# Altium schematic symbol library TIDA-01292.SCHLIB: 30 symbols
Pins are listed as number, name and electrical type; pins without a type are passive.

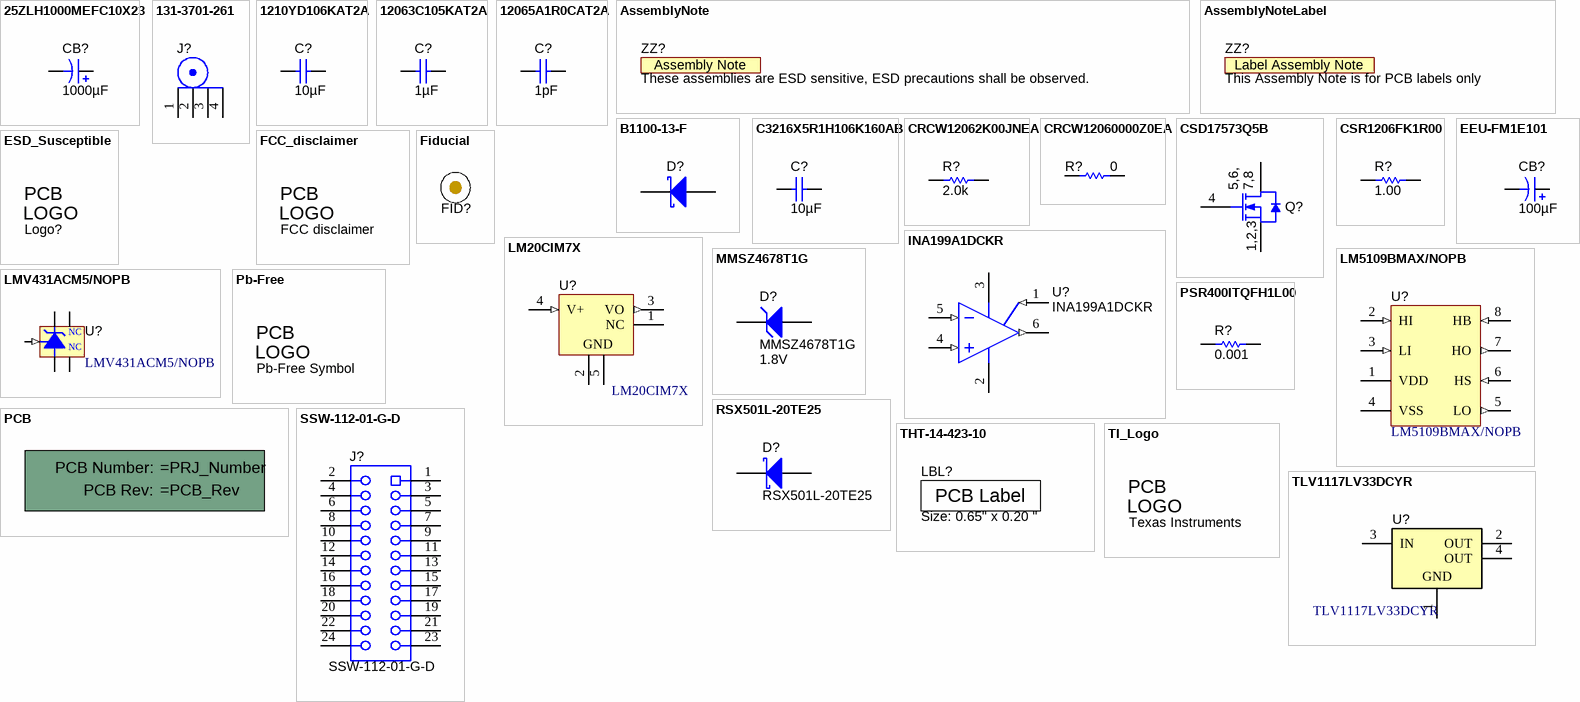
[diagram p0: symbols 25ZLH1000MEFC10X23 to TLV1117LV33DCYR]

## 25ZLH1000MEFC10X23
designator CB?  ValueDisplayed: 1000µF  (hidden comment: 25ZLH1000MEFC10X23)
CAP, AL, 1000 µF, 25 V, +/- 20%, 0.018 ohm, TH; Manufacturer: Rubycon; Polarized: Y; CompType: Capacitor; Value: 1000uF; U/M: EA; Cap_F: 0.001; Tolerance_%: 20; VDC_V: 25; Value2: 25V; ESR_ohm: 0.018; IRMS_A: 2.25; TaMin_C: -40; TaMax_C: 105; Cap_Case: 10x23mm; AEC Category: Q200
signal-integrity model Cap
simulation model Cap
footprint ZLH_1000x2300
pins: 1 +, 2 -

## 131-3701-261
designator J?  (value not drawn)
Connector, SMB,Vertical RCP 0-4GHz, 50 ohm, TH; Manufacturer: Emerson Network Power; SymbolCreator: X0208326
footprint CONN_131-3701-261
pins: 1, 2, 3, 4

## 1210YD106KAT2A
designator C?  ValueDisplayed: 10µF  (hidden comment: 1210YD106KAT2A)
CAP, CERM, 10 µF, 16 V, +/- 10%, X5R, 1210; Manufacturer: AVX; Polarized: N; CompType: Capacitor; Value: 10uF; U/M: EA; Cap_F: 0.00001; Tolerance_%: 10; Value1: Unknown; VDC_V: 16; Value2: 16V; TaMin_C: -55; TaMax_C: 85; Cap_Case: 1210; SizeArea_mm2: 8; SizeAreaWB_mm2: 14.7; SizeX_mm: 3.2; SizeY_mm: 2.5; SizeZ_mm: 2.8; AEC Category: Q200
signal-integrity model Cap
simulation model Cap
footprint 1210_280
pins: 1, 2

## 12063C105KAT2A
designator C?  ValueDisplayed: 1µF  (hidden comment: 12063C105KAT2A)
CAP, CERM, 1 µF, 25 V, +/- 10%, X7R, 1206; Manufacturer: AVX; Polarized: N; CompType: Capacitor; Value: 1uF; U/M: EA; Cap_F: 0.000001; Tolerance_%: 10; ESR_ohm: 0.013; Value1: 0.013 ohm; VDC_V: 25; Value2: 25V; TaMin_C: -55; TaMax_C: 125; Cap_Case: 1206; SizeArea_mm2: 5.12; SizeAreaWB_mm2: 10.92; SizeX_mm: 3.2; SizeY_mm: 1.6; SizeZ_mm: 1.35; AEC Category: Q200
signal-integrity model Cap
simulation model Cap
footprint 1206
footprint 1206M
footprint 1206L
pins: 1, 2

## 12065A1R0CAT2A
designator C?  ValueDisplayed: 1pF  (hidden comment: 12065A1R0CAT2A)
CAP, CERM, 1 pF, 50 V, +/- 25%, C0G/NP0, 1206; Manufacturer: AVX; Polarized: N; CompType: Capacitor; Value: 1pF; U/M: EA; Cap_F: 0.000000000001; Tolerance_%: 25; ESR_ohm: 15.566; Value1: 15.566 ohm; VDC_V: 50; Value2: 50V; TaMin_C: -55; TaMax_C: 125; Cap_Case: 1206; SizeArea_mm2: 5.12; SizeAreaWB_mm2: 10.92; SizeX_mm: 3.2; SizeY_mm: 1.6; SizeZ_mm: 1.35; AEC Category: Q200
signal-integrity model Cap
simulation model Cap
footprint 1206
footprint 1206M
footprint 1206L
pins: 1, 2

## AssemblyNote
designator ZZ?, comment These assemblies are ESD sensitive, ESD precautions shall be observed.  (no BOM)
SymbolCreator: codlsc; CompType: AssemblyNote
footprint AssemblyNote

## AssemblyNoteLabel
designator ZZ?, comment This Assembly Note is for PCB labels only  (no BOM)
SymbolCreator: a0412235
footprint AssemblyNoteLabel

## B1100-13-F
designator D?  (value not drawn)
Diode, Schottky, 100 V, 1 A, SMA; Manufacturer: Diodes Inc.; U/M: EA; Vf_V: 0.79; Value: 100V; Value1: 1A; Value2: 0.79V; Io_A: 1; Vr_V: 100; TJmax_C: 150; RJC_CperW: 25; SizeAreaWB_mm2: 37.3428; SizeArea_mm2: 16.3228; SizeX_mm: 5.59; SizeY_mm: 2.92; SizeZ_mm: 2.87; AEC Category: Q101
signal-integrity model Diode
simulation model DI_B1100
footprint SMA
pins: 1 K, 2 A

## C3216X5R1H106K160AB
designator C?  ValueDisplayed: 10µF  (hidden comment: C3216X5R1H106K160AB)
CAP, CERM, 10 µF, 50 V, +/- 10%, X5R, 1206; Manufacturer: TDK; Polarized: N; CompType: Capacitor; Value: 10uF; U/M: EA; Cap_F: 0.00001; Tolerance_%: 10; Value1: 0.002229 ohm; VDC_V: 50; Value2: 50V; ESR_ohm: 0.002229; IRMS_A: 4.85932; TaMin_C: -55; TaMax_C: 85; Cap_Case: 1206_180; SizeAreaWB_mm2: 10.92; SizeArea_mm2: 5.12; SizeX_mm: 3.2; SizeY_mm: 1.6; SizeZ_mm: 1.8; AEC Category: Q200
signal-integrity model Cap
simulation model Cap
footprint 1206_180
footprint 1206_180M
footprint 1206_180L
pins: 1, 2

## CRCW12062K00JNEA
designator R?  ValueDisplayed: 2.0k  (hidden comment: CRCW12062K00JNEA)
RES, 2.0 k, 5%, 0.25 W, 1206; Manufacturer: Vishay-Dale; CompType: Resistor; Value: 2.0k; Res_ohm: 2000; Value_Code: 2k00; Tolerance_%: 5; Power_W: 0.25; Value2: 0.25W; VDC_V: 200; TempCo: 200 ppm/C; SizeArea_mm2: 5.12; SizeX_mm: 3.2; SizeY_mm: 1.6; SizeZ_mm: 1.35; EIA_Code: E24; U/M: EA; AEC Category: Q200
signal-integrity model Resistor
simulation model Resistor
footprint 1206
footprint 1206M
footprint 1206L
pins: 1, 2

## CRCW12060000Z0EA
designator R?  ValueDisplayed: 0  (hidden comment: CRCW12060000Z0EA)
RES, 0, 5%, 0.25 W, 1206; Manufacturer: Vishay-Dale; CompType: Resistor; Value: 0; Value_Code: 0000; Tolerance_%: 5; Power_W: 0.25; Value2: 0.25W; VDC_V: 200; TempCo: 200 ppm/C; SizeArea_mm2: 5.12; SizeX_mm: 3.2; SizeY_mm: 1.6; SizeZ_mm: 1.35; EIA_Code: E24; U/M: EA; AEC Category: Q200
signal-integrity model Resistor
simulation model Resistor
footprint 1206
footprint 1206M
footprint 1206L
pins: 1, 2

## CSD17573Q5B
designator Q?  (value not drawn)
MOSFET, N-CH, 30 V, 100 A, SON 5x6mm; Manufacturer: Texas Instruments; Alternate Manufacturer: None; U/M: EA; ChType: N; Value: 30V; VdsMax_V: 30; Value1: 0.00145 ohm; Rdson45_ohm: 0.00145; Value2: 49 nC; QgTyp_nC: 49; Vgs_V: 20; IdsMax_A: 100; SizeAreaWB_mm2: 57.51; SizeArea_mm2: 31.11; SizeX_mm: 6.1; SizeY_mm: 5.1; SizeZ_mm: 1.05; AEC Category: Q101
footprint TRANS_NexFET_Q5B
pins: 1 S, 2 S, 3 S, 4 G, 5 D, 6 D, 7 D, 8 D
1 alternate drawing of the same symbol

## CSR1206FK1R00
designator R?  ValueDisplayed: 1.00  (hidden comment: CSR1206FK1R00)
RES, 1.00, 1%, 0.5 W, 1206; Manufacturer: Stackpole Electronics Inc; CompType: Resistor; Value: 1.00; Res_ohm: 1; Value_Code: 1R00; Power_W: 0.5; Value2: 0.5W; TempCo: 100 ppm/C; SizeArea_mm2: 5.12; SizeX_mm: 3.2; SizeY_mm: 1.6; SizeZ_mm: 1.35; EIA_Code: E96; U/M: EA; AEC Category: Q200
signal-integrity model Resistor
simulation model Resistor
footprint 1206
footprint 1206M
footprint 1206L
pins: 1, 2

## EEU-FM1E101
designator CB?  ValueDisplayed: 100µF  (hidden comment: EEU-FM1E101)
CAP, AL, 100 µF, 25 V, +/- 20%, 0.13 ohm, TH; Manufacturer: Panasonic; Polarized: Y; CompType: Capacitor; Value: 100uF; U/M: EA; Cap_F: 0.0001; Tolerance_%: 20; VDC_V: 25; Value2: 25V; ESR_ohm: 0.13; IRMS_A: 0.455; TaMin_C: -40; TaMax_C: 105; Cap_Case: 6.3x11.2; AEC Category: Q200; AEC Qualified: N
signal-integrity model Cap
simulation model Cap
footprint FM_630x1120
pins: 1 +, 2 -

## ESD_Susceptible
designator Logo?, comment ESD Susceptible  (value not drawn)  (no BOM)
ESD Susceptible Symbol; SymbolCreator: a0412235
footprint ESD_Overlay_Large
footprint ESD_Overlay_Medium
footprint ESD_Overlay_Small

## FCC_disclaimer
designator Logo?, comment FCC disclaimer  (no BOM)
FCC_disclaimer; SymbolCreator: codlsc
footprint FCC_disclaimer
footprint FCC_disclaimer_stacked

## Fiducial
designator FID?  (value not drawn)
Fiducial mark.  There is nothing to buy or mount.; SymbolCreator: codlsc
footprint Fiducial10-30
footprint Fiducial10-20
footprint Fiducial15-30
footprint Fiducial20-40
footprint Fiducial6.4-20

## INA199A1DCKR
designator U?
Voltage Output, High or Low Side Measurement, Bi-Directional Zerø-Drift Series Current-Shunt Monitor, DCK0006A (SOT-6); Alternate PartNumber: INA199A1DCKT; Manufacturer: Texas Instruments; SymbolCreator: a0411947; SizeArea_mm2: 4.2; SizeAreaWB_mm2: 9.3; SizeX_mm: 2.1; SizeY_mm: 2; SizeZ_mm: 1.1; CompType: IC; U/M: EA
footprint DCK0006A_N
footprint DCK0006A_M
footprint DCK0006A_L
pins: 1 REF (in), 2 GND (power), 3 VCC (power), 4 IN+ (in), 5 IN- (in), 6 OUT (out)
1 alternate drawing of the same symbol

## LM20CIM7X
designator U?
2.4V, 10µA Temperature Sensor, 5-pin SC-70 Micro SMD; Manufacturer: Texas Instruments; PackageTopMarking: T2C*XTT; PowerWise: N; CompType: Temp Sensor IC
footprint MAA05A_N (SOT353, 5-Leads, Body 2x1.3mm, Pitch 0.65mm, Lead Span 2.1mm, IPC Medium Density)
footprint MAA05A_L (SOT353, 5-Leads, Body 2x1.3mm, Pitch 0.65mm, Lead Span 2.1mm, IPC High Density)
footprint MAA05A_M (SOT353, 5-Leads, Body 2x1.3mm, Pitch 0.65mm, Lead Span 2.1mm, IPC Low Density)
pins: 1 NC "Not Connected", 2 GND (power) "Ground", 3 VO (out), 4 V+ (in), 5 GND (power) "Ground"

## LM5109BMAX/NOPB
designator U?
High Voltage 1A Peak Half Bridge Gate Driver, 8-pin Narrow SOIC, Pb-Free; Manufacturer: Texas Instruments; PackageTopMarking: NSZXTT*L5109*BMA; PowerWise: N; CompType: MiscPower
footprint M08A_N (SOIC, 8-Leads, Body 4.9x3.9mm, Pitch 1.27mm, IPC Medium Density)
footprint M08A_L (SOIC, 8-Leads, Body 4.9x3.9mm, Pitch 1.27mm, IPC High Density)
footprint M08A_M (SOIC, 8-Leads, Body 4.9x3.9mm, Pitch 1.27mm, IPC Low Density)
pins: 1 VDD (power), 2 HI (in), 3 LI (in), 4 VSS (power), 5 LO (out), 6 HS (in), 7 HO (out), 8 HB (in)

## LMV431ACM5/NOPB
designator U?
Low-Voltage (1.24V) Adjustable Precision Shunt Regulators, 5-pin SOT-23, Pb-Free; Manufacturer: Texas Instruments; PackageTopMarking: N09A*XTT; PowerWise: N; CompType: MiscPower
footprint MF05A_N (SOT23, 5-Leads, Body 2.9x1.6mm, Pitch 0.95mm, Lead Span 2.8mm, IPC Medium Density)
footprint MF05A_L (SOT23, 5-Leads, Body 2.9x1.6mm, Pitch 0.95mm, Lead Span 2.8mm, IPC High Density)
footprint MF05A_M (SOT23, 5-Leads, Body 2.9x1.6mm, Pitch 0.95mm, Lead Span 2.8mm, IPC Low Density)
pins: 1 NC, 2 NC, 3 K, 4 REF (in), 5 A

## MMSZ4678T1G
designator D?  value 1.8V
Diode, Zener, 1.8 V, 500 mW, SOD-123; Manufacturer: ON Semiconductor; SymbolCreator: a0412235; U/M: EA; Power_W: 0.5; Vz_V: 1.8; Value1: 0.5W; RJA_CperW: 340; SizeAreaWB_mm2: 13.095; SizeArea_mm2: 6.545; SizeX_mm: 3.85; SizeY_mm: 1.7; SizeZ_mm: 1.35; AEC Category: Q101
signal-integrity model Diode
footprint SOD-123
pins: 1 K, 2 A

## Pb-Free
designator Logo?, comment Pb-Free Symbol  (no BOM)
SymbolCreator: a0412235
footprint Pb-Free_Overlay_Medium
footprint Pb-Free_Overlay_Small

## PCB
designator !PCB?, comment Printed Circuit Board  (value not drawn)  (mechanical)
Manufacturer: Any; SymbolCreator: a0412235; CompType: PCB
1 alternate drawing of the same symbol

## PSR400ITQFH1L00
designator R?  ValueDisplayed: 0.001  (hidden comment: PSR400ITQFH1L00)
RES, 0.001, 1%, 4 W, AEC-Q200 Grade 0, 10x5.2mm; Manufacturer: Rohm; CompType: Resistor; Value: 0.001; Value_Code: 1L000; Tolerance_%: 1; Power_W: 4; Value2: 4W; TempCo: 75 ppm/C; SizeArea_mm2: 52; SizeAreaWB_mm2: 86.4; SizeX_mm: 10; SizeY_mm: 5.2; SizeZ_mm: 1.05; EIA_Code: E96; U/M: EA; AEC Category: Q200; AEC Qualified: Y; AEC Grade: 0
signal-integrity model Resistor
simulation model Resistor
footprint 3921_105
pins: 1, 2

## RSX501L-20TE25
designator D?
Diode, Schottky, 20 V, 5 A, SMA; Manufacturer: Rohm; U/M: EA; Vf_V: 0.39; Value: 20V; Value1: 5A; Value2: 0.39V; Io_A: 5; Vr_V: 20; TJmax_C: 125; SizeAreaWB_mm2: 37.3428; SizeArea_mm2: 16.3228; SizeX_mm: 5.59; SizeY_mm: 2.92; SizeZ_mm: 2.87; AEC Category: Q101
signal-integrity model Diode
footprint SMA
pins: 1 K, 2 A

## SSW-112-01-G-D
designator J?
Receptacle, 12x2, 2.54mm, Gold, TH; Manufacturer: Samtec; SymbolCreator: a0799628; Pitch_mm: 2.54; Gender: Female; Row_Count: 2; Current_A: 5.7; Cert_CSA: Y
footprint Samtec_SSW-112-01-x-D
pins: 1, 2, 3, 4, 5, 6, 7, 8, 9, 10, 11, 12, 13, 14, 15, 16, 17, 18, 19, 20, 21, 22, 23, 24

## THT-14-423-10
designator LBL?, comment Size: 0.65" x 0.20 "
Thermal Transfer Printable Labels, 0.650" W x 0.200" H - 10,000 per roll; Manufacturer: Brady; PartNumber: THT-14-423-10; SymbolCreator: a0412235; CompType: Label
footprint Label_650x200

## TI_Logo
designator Logo?, comment Texas Instruments  (no BOM)
Texas Instrument Corporate Signature; SymbolCreator: codlsc
footprint TI_Stacked_SolderMask_Medium
footprint TI_Stacked_SolderMask_Small
footprint TI_Stacked_Overlay_Medium
footprint TI_Stacked_Overlay_Small
footprint TI_Horizontal_SolderMask_Medium
footprint TI_Horizontal_SolderMask_Small
footprint TI_Horizontal_Overlay_Medium
footprint TI_Horizontal_Overlay_Small
footprint TI_Symbol_SolderMask_Small
footprint TI_Symbol_Overlay_Medium
footprint TI_Symbol_Overlay_Small
footprint TI_Symbol_SolderMask_Medium

## TLV1117LV33DCYR
designator U?
Single Output LDO, 1 A, Fixed 3.3 V Output, 2 to 5.5 V Input, 4-pin SOT-223 (DCY), -40 to 125 degC, Green (RoHS & no Sb/Br); Manufacturer: Texas Instruments; Alternate PartNumber: Equivalent; Accuracy(%): 2; Fixed Output Options(V): 3.3; Iout(Max)(A): 1; Iq(Typ)(mA): 0.05; SubFamily: Single Channel LDO; Vdo(Typ)(mV): 1200; Vin(Max)(V): 5.5
footprint DCY0004A_N (SOT223, 4-Leads, Body 6.5x3.5mm, Pitch 2.3mm, IPC Medium Density)
footprint DCY0004A_L (SOT223, 4-Leads, Body 6.5x3.5mm, Pitch 2.3mm, IPC High Density)
footprint DCY0004A_M (SOT223, 4-Leads, Body 6.5x3.5mm, Pitch 2.3mm, IPC Low Density)
pins: 1 GND (power) "Ground pin", 2 OUT (power) "Regulated output voltage pin.", 3 IN (power) "Input pin.", 4 OUT (power) "Regulated output voltage pin."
